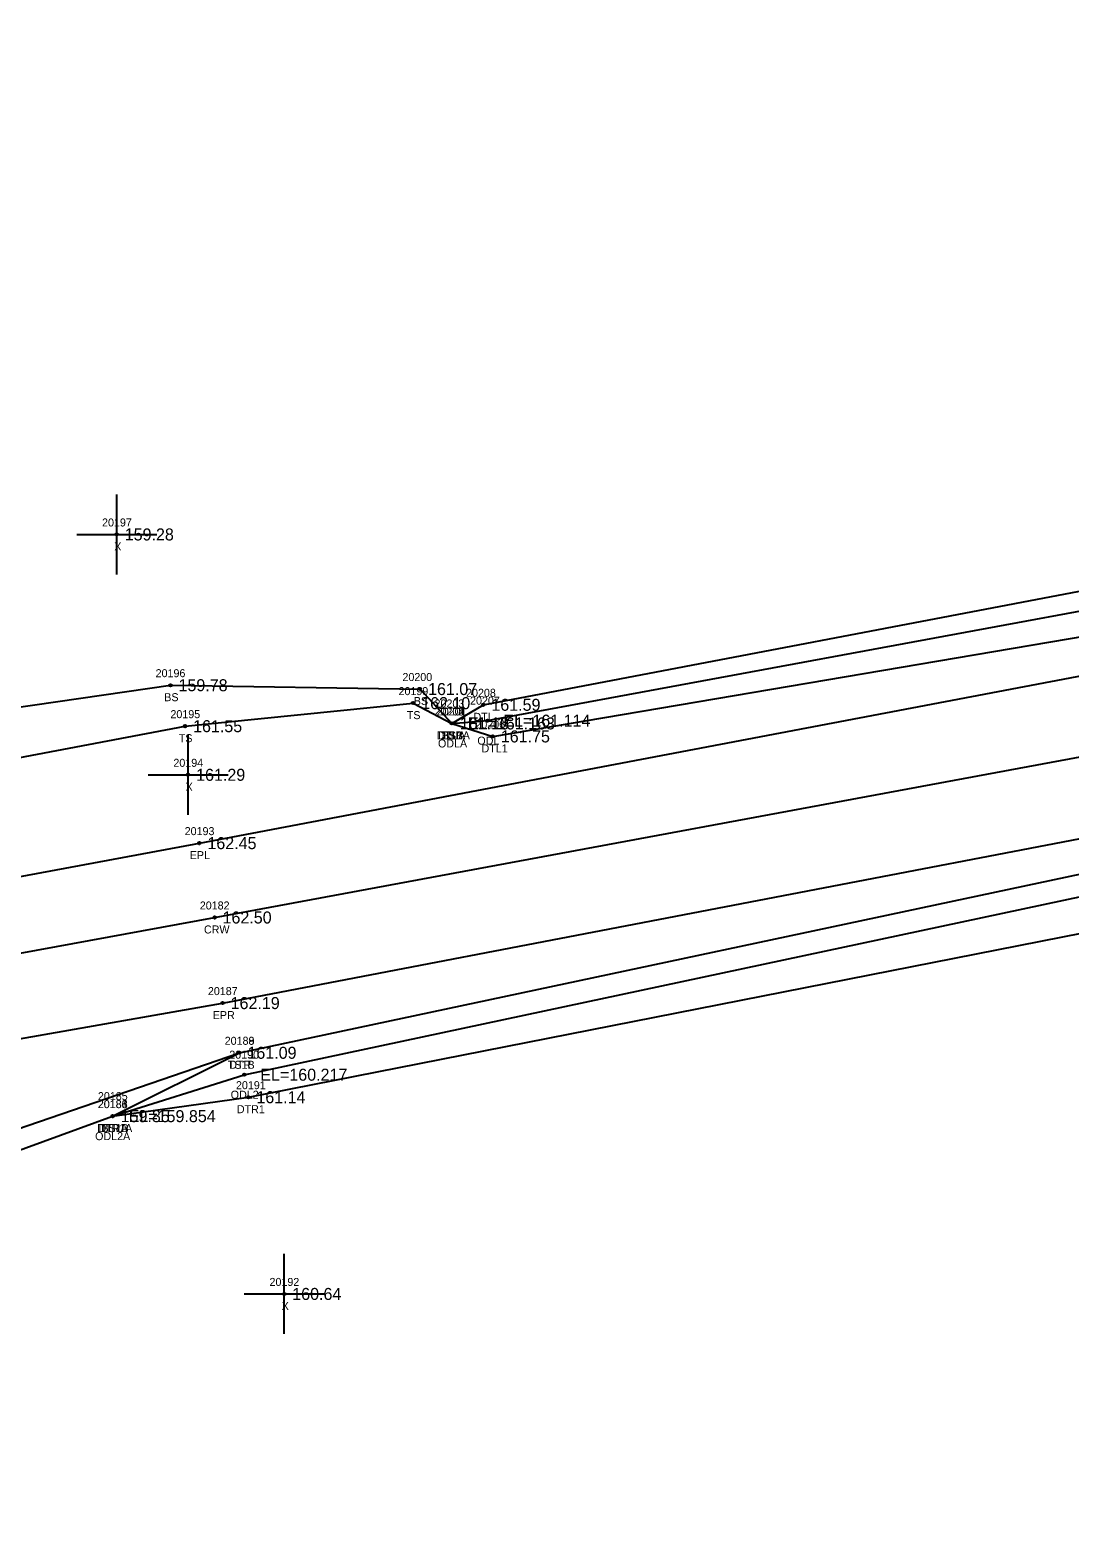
# Model space of a CAD drawing. Extents: x 2381545 to 2382928, y 1029933 to 1030589.
# Drawn here: x 2382413.9 to 2382543.8, y 1030337.6 to 1030525.8 of the extents above; entities that cross this region are included whole.
import ezdxf

# ---------------------------------------------------------------- set-up
doc = ezdxf.new("R2010")
doc.units = 0
for name, color, linetype in [('RD_DTM_BkLn1', 7, 'Continuous'), ('RD_DTM_BkLn2', 7, 'Continuous'), ('RD_DTM_BkLn_txCode', 7, 'Continuous'), ('RD_EX_H2O', 7, 'Continuous'), ('RD_EX_H2O_txCode', 7, 'Continuous'), ('RD_EX_Misc', 7, 'Continuous'), ('RD_EX_Misc_txCode', 7, 'Continuous'), ('RD_EX_Road', 7, 'Continuous'), ('RD_EX_Road_txCode', 7, 'Continuous'), ('RD_EX_TX_H2O_ELEV', 7, 'Continuous'), ('RD_EX_TX_Misc_ELEV', 7, 'Continuous'), ('RD_EX_TX_Road_ELEV', 7, 'Continuous'), ('RD_HC_Survey_ELEV', 7, 'Continuous'), ('RD_HC_Survey_txCode', 7, 'Continuous'), ('RD_SMD_Locator', 7, 'Continuous')]:
    doc.layers.add(name, color=color, linetype=linetype)

msp = doc.modelspace()

# ---------------------------------------------------------------- linework, layer by layer
at = {"layer": 'RD_DTM_BkLn1'}
msp.add_lwpolyline([(2382237.83, 1030377.97), (2382343.9, 1030397.77), (2382436.97, 1030414.87), (2382557.72, 1030437.27), (2382666.29, 1030458.08), (2382780.92, 1030480.13), (2382908.6, 1030503.95)], dxfattribs=at)
at = {"layer": 'RD_DTM_BkLn2'}
for points in [[(2382228.76, 1030407.08), (2382256.33, 1030426.45), (2382278.98, 1030422.43), (2382339.75, 1030430.63), (2382431.47, 1030443.9), (2382462.65, 1030443.42), (2382466.62, 1030439.12)], [(2382235.13, 1030386.42), (2382230.84, 1030394.95), (2382233.48, 1030405.21), (2382255.02, 1030418.7), (2382277.57, 1030415.22), (2382339.26, 1030420.97), (2382433.29, 1030438.78), (2382461.79, 1030441.66), (2382466.62, 1030439.12)], [(2382241.1, 1030367.72), (2382237.31, 1030356.38), (2382242.21, 1030353.56), (2382262.35, 1030353.01), (2382291.43, 1030352.47), (2382349.66, 1030366.91), (2382440.08, 1030397.96)], [(2382240.51, 1030349.49), (2382260.46, 1030337.58), (2382294.55, 1030349.23), (2382350.1, 1030362.95), (2382424.24, 1030390.04)]]:
    msp.add_lwpolyline(points, dxfattribs=at)
at = {"layer": 'RD_EX_H2O'}
for points in [[(2382466.62, 1030439.12), (2382470.56, 1030441.45), (2382553.99, 1030457.35), (2382661.6, 1030479.57), (2382777.69, 1030501.62), (2382905.21, 1030525.77)], [(2382466.62, 1030439.12), (2382471.06, 1030439.47), (2382554.93, 1030454.98), (2382662.31, 1030475.15), (2382778.18, 1030497.02), (2382905.16, 1030521.52)], [(2382466.62, 1030439.12), (2382471.74, 1030437.5), (2382555.22, 1030451.65), (2382662.97, 1030471.73), (2382778.37, 1030493.62), (2382905.48, 1030518.64)], [(2382424.24, 1030390.04), (2382440.08, 1030397.96), (2382560.33, 1030423.53), (2382668.22, 1030444.25), (2382764.75, 1030462.61), (2382766.55, 1030456.54)], [(2382424.24, 1030390.04), (2382440.69, 1030395.22), (2382560.27, 1030420.72), (2382668.78, 1030440.95), (2382763.32, 1030459.02)], [(2382424.24, 1030390.04), (2382441.2, 1030392.41), (2382561.56, 1030416.11), (2382669.3, 1030434.96), (2382766.55, 1030456.54)]]:
    msp.add_lwpolyline(points, dxfattribs=at)
at = {"layer": 'RD_EX_Misc'}
for p, q in [((2382424.75, 1030457.74), (2382424.75, 1030467.74)), ((2382419.75, 1030462.74), (2382429.75, 1030462.74)), ((2382433.67, 1030427.7), (2382433.67, 1030437.7)), ((2382428.67, 1030432.7), (2382438.67, 1030432.7)), ((2382445.68, 1030362.82), (2382445.68, 1030372.82)), ((2382440.68, 1030367.82), (2382450.68, 1030367.82))]:
    msp.add_line(p, q, dxfattribs=at)
at = {"layer": 'RD_EX_Road'}
for points in [[(2382237.83, 1030377.97), (2382235.13, 1030386.42), (2382342.38, 1030406.92), (2382435.08, 1030424.16), (2382555.51, 1030447.01), (2382663.83, 1030467.83), (2382778.84, 1030489.45), (2382906.57, 1030513.81)], [(2382237.83, 1030377.97), (2382241.1, 1030367.72), (2382346.41, 1030388.08), (2382437.98, 1030404.17), (2382559.51, 1030427.48), (2382667.4, 1030448.54), (2382782.14, 1030469.8), (2382910.48, 1030494.44)]]:
    msp.add_lwpolyline(points, dxfattribs=at)
at = {"layer": 'RD_SMD_Locator'}
for centre in [(2382424.75, 1030462.74), (2382431.47, 1030443.9), (2382462.65, 1030443.42), (2382461.79, 1030441.66), (2382470.56, 1030441.45), (2382433.29, 1030438.78), (2382466.62, 1030439.12), (2382466.62, 1030439.12), (2382466.62, 1030439.12), (2382466.62, 1030439.12), (2382466.62, 1030439.12), (2382471.06, 1030439.47), (2382471.74, 1030437.5), (2382433.67, 1030432.7), (2382435.08, 1030424.16), (2382436.97, 1030414.87), (2382437.98, 1030404.17), (2382440.08, 1030397.96), (2382440.08, 1030397.96), (2382440.69, 1030395.22), (2382441.2, 1030392.41), (2382424.24, 1030390.04), (2382424.24, 1030390.04), (2382424.24, 1030390.04), (2382424.24, 1030390.04), (2382445.68, 1030367.82)]:
    msp.add_circle(centre, 0.15, dxfattribs=at)

# ---------------------------------------------------------------- texts
at = {"layer": 'RD_DTM_BkLn_txCode'}
for s, p in [('20196', (2382429.61, 1030444.9)), ('20200', (2382460.45, 1030444.42)), ('BS', (2382430.69, 1030441.9)), ('20199', (2382459.96, 1030442.66)), ('20195', (2382431.46, 1030439.78)), ('BS', (2382461.87, 1030441.42)), ('20202', (2382464.46, 1030440.12)), ('20201', (2382464.74, 1030440.12)), ('TS', (2382460.99, 1030439.66)), ('TS', (2382432.5, 1030436.78)), ('TSB', (2382465.35, 1030437.12)), ('BSB', (2382465.37, 1030437.12)), ('20188', (2382438.24, 1030398.96)), ('TS1B', (2382438.64, 1030395.96)), ('20183', (2382422.4, 1030391.04)), ('BS1B', (2382422.82, 1030388.04))]:
    msp.add_text(s, height=1, dxfattribs=at).set_placement(p)
at = {"layer": 'RD_EX_H2O_txCode'}
for s, p in [('20208', (2382468.4, 1030442.45)), ('20203', (2382464.46, 1030441.12)), ('20204', (2382464.46, 1030440.12)), ('20205', (2382464.46, 1030440.12)), ('20207', (2382468.9, 1030441.47)), ('DTL', (2382469.32, 1030439.45)), ('20206', (2382469.56, 1030438.5)), ('DTL1A', (2382464.72, 1030437.12)), ('ODLA', (2382464.89, 1030436.12)), ('DTLA', (2382464.89, 1030437.12)), ('ODL', (2382469.81, 1030436.47)), ('DTL1', (2382470.33, 1030435.5)), ('20189', (2382438.24, 1030398.96)), ('20190', (2382438.81, 1030397.22)), ('DTR', (2382438.81, 1030395.96)), ('20191', (2382439.65, 1030393.41)), ('20186', (2382422.38, 1030391.04)), ('20185', (2382422.4, 1030392.04)), ('20184', (2382422.4, 1030391.04)), ('ODL2', (2382438.99, 1030392.22)), ('DTR1', (2382439.76, 1030390.41)), ('ODL2A', (2382422.05, 1030387.04)), ('DTR1A', (2382422.31, 1030388.04)), ('DTRA', (2382422.48, 1030388.04))]:
    msp.add_text(s, height=1, dxfattribs=at).set_placement(p)
at = {"layer": 'RD_EX_Misc_txCode'}
for s, p in [('20197', (2382422.92, 1030463.74)), ('X', (2382424.44, 1030460.74)), ('20194', (2382431.83, 1030433.7)), ('X', (2382433.35, 1030430.7)), ('20192', (2382443.84, 1030368.82)), ('X', (2382445.36, 1030365.82))]:
    msp.add_text(s, height=1, dxfattribs=at).set_placement(p)
at = {"layer": 'RD_EX_Road_txCode'}
for s, p in [('20193', (2382433.24, 1030425.16)), ('EPL', (2382433.87, 1030422.16)), ('20187', (2382436.14, 1030405.17)), ('EPR', (2382436.75, 1030402.17))]:
    msp.add_text(s, height=1, dxfattribs=at).set_placement(p)
at = {"layer": 'RD_EX_TX_H2O_ELEV'}
for s, p in [('161.59', (2382471.56, 1030440.7)), ('161.16', (2382467.62, 1030438.37)), ('161.16', (2382467.62, 1030438.37)), ('EL=161.163', (2382468.62, 1030438.37)), ('EL=161.114', (2382473.06, 1030438.72)), ('161.75', (2382472.74, 1030436.75)), ('161.09', (2382441.08, 1030397.21)), ('EL=160.217', (2382442.69, 1030394.47)), ('161.14', (2382442.2, 1030391.66)), ('159.85', (2382425.24, 1030389.29)), ('159.85', (2382425.24, 1030389.29)), ('EL=159.854', (2382426.24, 1030389.29))]:
    msp.add_text(s, height=1.5, dxfattribs=at).set_placement(p)
at = {"layer": 'RD_EX_TX_Misc_ELEV'}
for s, p in [('159.28', (2382425.75, 1030461.99)), ('159.78', (2382432.47, 1030443.15)), ('161.07', (2382463.65, 1030442.67)), ('162.10', (2382462.79, 1030440.91)), ('161.55', (2382434.29, 1030438.03)), ('161.16', (2382467.62, 1030438.37)), ('161.16', (2382467.62, 1030438.37)), ('161.29', (2382434.67, 1030431.95)), ('161.09', (2382441.08, 1030397.21)), ('159.85', (2382425.24, 1030389.29)), ('160.64', (2382446.68, 1030367.07))]:
    msp.add_text(s, height=1.5, dxfattribs=at).set_placement(p)
at = {"layer": 'RD_EX_TX_Road_ELEV'}
for s, p in [('162.45', (2382436.08, 1030423.41)), ('162.19', (2382438.98, 1030403.42))]:
    msp.add_text(s, height=1.5, dxfattribs=at).set_placement(p)
at = {"layer": 'RD_HC_Survey_ELEV'}
msp.add_text('162.50', height=1.5, dxfattribs=at).set_placement((2382437.97, 1030414.12))
at = {"layer": 'RD_HC_Survey_txCode'}
for s, p in [('20182', (2382435.13, 1030415.87)), ('CRW', (2382435.65, 1030412.87))]:
    msp.add_text(s, height=1, dxfattribs=at).set_placement(p)

doc.saveas('drawing.dxf')
